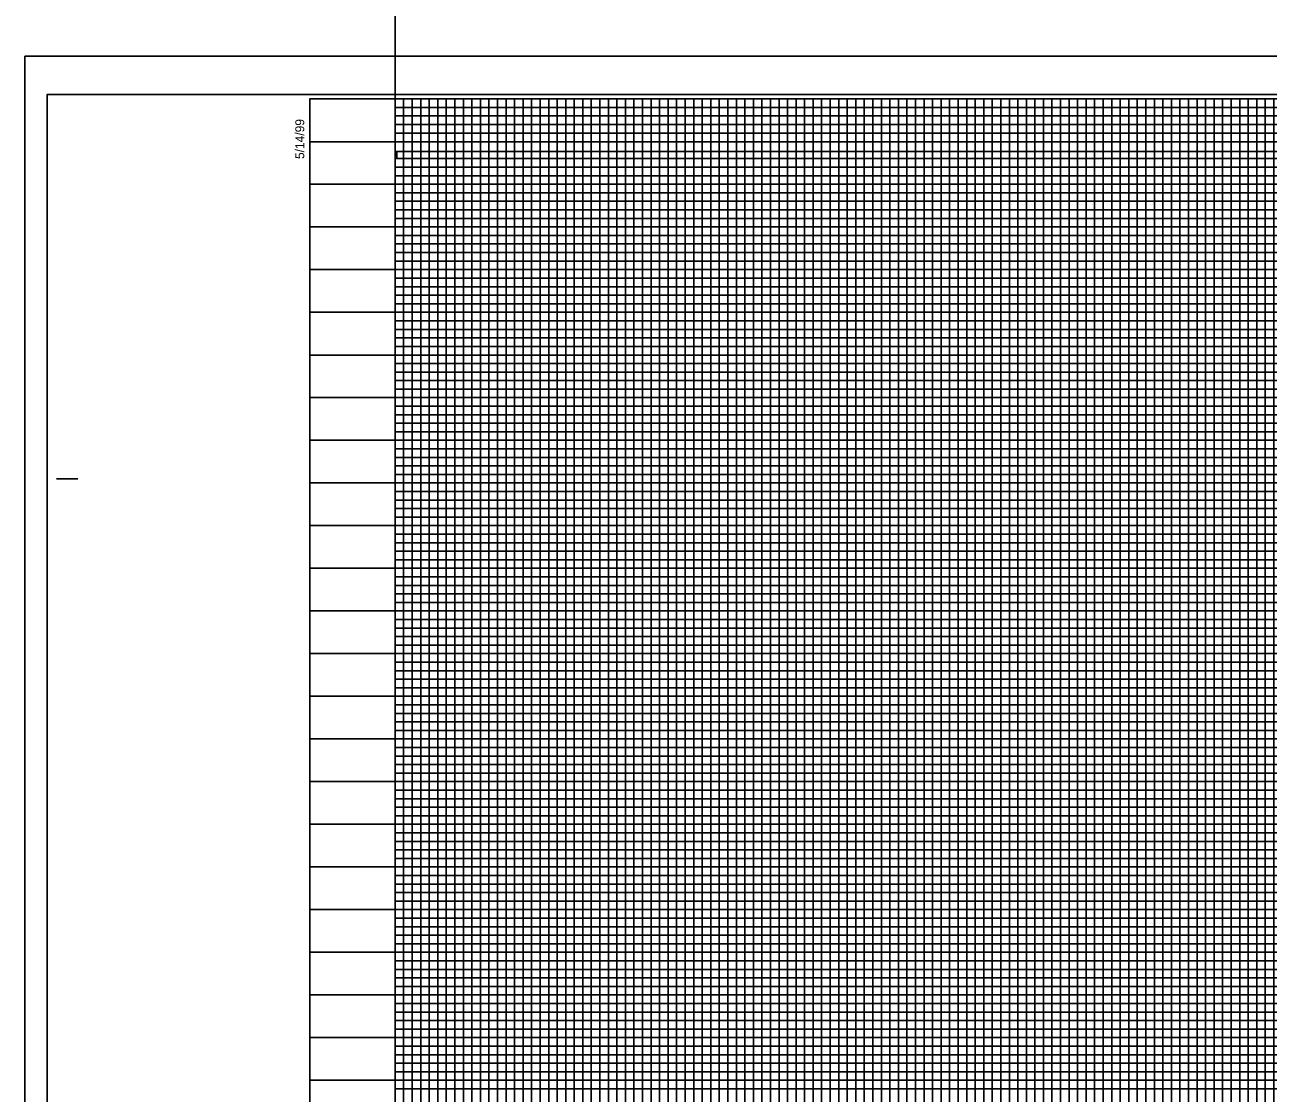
# Model space of a CAD drawing. Extents: x 2345490 to 2436403, y 465165 to 573888.
# Drawn here: x 2381463 to 2382192, y 536643 to 537269 of the extents above; entities that cross this region are included whole.
import ezdxf

# ---------------------------------------------------------------- set-up
doc = ezdxf.new("R2010")
doc.units = 0
for name, color, linetype in [('Old_Level_18', 7, 'Continuous'), ('Old_Level_41', 7, 'Continuous'), ('Old_Level_42', 7, 'Continuous'), ('Old_Level_43', 7, 'Continuous'), ('Old_Level_50', 7, 'Continuous'), ('Old_Level_51', 7, 'Continuous'), ('Old_Level_63', 7, 'Continuous')]:
    doc.layers.add(name, color=color, linetype=linetype)

msp = doc.modelspace()

# ---------------------------------------------------------------- linework, layer by layer
at = {"layer": 'Old_Level_18'}
msp.add_lwpolyline([(2383130.454, 537225.68175), (2381630.454, 537225.68175), (2381630.454, 536175.68175), (2383130.454, 536175.68175)], close=True, dxfattribs=at)
at = {"layer": 'Old_Level_41'}
msp.add_line((2381481.954, 537003.18175), (2381494.454, 537003.18175), dxfattribs=at)
for points in [[(2381630.454, 537225.68175), (2381680.454, 537225.68175), (2381680.454, 536200.68175), (2381730.454, 536200.68175), (2381730.454, 537225.68175), (2381780.454, 537225.68175), (2381780.454, 536200.68175), (2381830.454, 536200.68175), (2381830.454, 537225.68175), (2381880.454, 537225.68175), (2381880.454, 536200.68175), (2381930.454, 536200.68175), (2381930.454, 537225.68175), (2381980.454, 537225.68175), (2381980.454, 536200.68175), (2382030.454, 536200.68175), (2382030.454, 537225.68175), (2382080.454, 537225.68175), (2382080.454, 536200.68175), (2382130.454, 536200.68175), (2382130.454, 537225.68175), (2382180.454, 537225.68175), (2382180.454, 536200.68175), (2382230.454, 536200.68175)], [(2381705.454, 536200.68175), (2381705.454, 537225.68175), (2381755.454, 537225.68175), (2381755.454, 536200.68175), (2381805.454, 536200.68175), (2381805.454, 537225.68175), (2381855.454, 537225.68175), (2381855.454, 536200.68175), (2381905.454, 536200.68175), (2381905.454, 537225.68175), (2381955.454, 537225.68175), (2381955.454, 536200.68175), (2382005.454, 536200.68175), (2382005.454, 537225.68175), (2382055.454, 537225.68175), (2382055.454, 536200.68175), (2382105.454, 536200.68175), (2382105.454, 537225.68175), (2382155.454, 537225.68175), (2382155.454, 536200.68175), (2382205.454, 536200.68175)], [(2381630.454, 537175.68175), (2382930.404, 537175.68175)], [(2382930.404, 537125.68175), (2381630.454, 537125.68175), (2381630.454, 537075.63175), (2383130.454, 537075.63175)], [(2383130.454, 537050.68175), (2381630.454, 537050.68175), (2381630.454, 537100.68175), (2382930.404, 537100.68175)], [(2383130.454, 537025.68175), (2381630.454, 537025.68175), (2381630.454, 536975.68175), (2383130.454, 536975.68175)], [(2383130.454, 536950.68175), (2381630.454, 536950.68175), (2381630.454, 537000.68175), (2383130.454, 537000.68175)], [(2383130.454, 536925.68175), (2381630.454, 536925.68175), (2381630.454, 536875.68175), (2383130.454, 536875.68175)], [(2383130.454, 536825.68175), (2381630.454, 536825.68175), (2381630.454, 536775.68175), (2383130.454, 536775.68175)], [(2383130.454, 536725.68175), (2381630.454, 536725.68175), (2381630.454, 536675.68175), (2383130.454, 536675.68175)]]:
    msp.add_lwpolyline(points, dxfattribs=at)
at = {"layer": 'Old_Level_42'}
for points in [[(2382930.404, 537150.68175), (2381630.554, 537150.68175), (2381630.554, 537200.63175), (2382930.404, 537200.63175)], [(2383130.454, 536850.68175), (2381630.454, 536850.68175), (2381630.454, 536900.68175), (2383130.454, 536900.68175)], [(2383130.454, 536750.68175), (2381630.454, 536750.68175), (2381630.454, 536800.68175), (2383130.454, 536800.68175)], [(2383130.454, 536650.68175), (2381630.454, 536650.68175), (2381630.454, 536700.68175), (2383130.454, 536700.68175)]]:
    msp.add_lwpolyline(points, dxfattribs=at)
at = {"layer": 'Old_Level_43'}
for p, q in [((2383080.454, 537045.68175), (2381680.454, 537045.68175)), ((2381680.454, 537045.68175), (2381680.454, 537040.68175)), ((2381680.454, 537040.68175), (2383080.454, 537040.68175)), ((2383080.454, 537020.68175), (2381680.454, 537020.68175))]:
    msp.add_line(p, q, dxfattribs=at)
for points in [[(2381685.454, 537225.68175), (2381690.454, 537225.68175), (2381695.454, 537225.68175), (2381700.454, 537225.68175), (2381710.454, 537225.68175), (2381677.404, 537225.68175), (2381682.404, 537225.68175), (2381640.454, 537225.68175), (2381645.454, 537225.68175), (2381650.454, 537225.68175), (2381660.454, 537225.68175), (2381665.454, 537225.68175), (2381670.454, 537225.68175), (2381675.454, 537225.68175), (2381685.454, 537225.68175), (2381685.454, 536200.68175)], [(2382930.404, 537220.68175), (2381680.454, 537220.68175), (2381680.454, 537215.68175), (2382930.404, 537215.68175)], [(2381690.454, 536200.68175), (2381690.454, 537225.68175), (2381695.454, 537225.68175), (2381695.454, 536200.68175)], [(2381700.454, 536200.68175), (2381700.454, 537225.68175), (2381710.454, 537225.68175), (2381710.454, 536200.68175)], [(2381715.454, 536200.68175), (2381715.454, 537225.68175), (2381720.454, 537225.68175), (2381720.454, 536200.68175)], [(2381725.454, 536200.68175), (2381725.454, 537225.68175), (2381735.454, 537225.68175), (2381735.454, 536200.68175)], [(2381740.454, 536200.68175), (2381740.454, 537225.68175), (2381745.454, 537225.68175), (2381745.454, 536200.68175)], [(2381750.454, 536200.68175), (2381750.454, 537225.68175), (2381760.454, 537225.68175), (2381760.454, 536200.68175)], [(2381765.454, 536200.68175), (2381765.454, 537225.68175), (2381770.454, 537225.68175), (2381770.454, 536200.68175)], [(2381775.454, 536200.68175), (2381775.454, 537225.68175), (2381785.454, 537225.68175), (2381785.454, 536200.68175)], [(2381790.454, 536200.68175), (2381790.454, 537225.68175), (2381795.454, 537225.68175), (2381795.454, 536200.68175)], [(2381800.454, 536200.68175), (2381800.454, 537225.68175), (2381810.454, 537225.68175), (2381810.454, 536200.68175)], [(2381815.454, 536200.68175), (2381815.454, 537225.68175), (2381820.454, 537225.68175), (2381820.454, 536200.68175)], [(2381825.454, 536200.68175), (2381825.454, 537225.68175), (2381835.454, 537225.68175), (2381835.454, 536200.68175)], [(2381840.454, 536200.68175), (2381840.454, 537225.68175), (2381845.454, 537225.68175), (2381845.454, 536200.68175)], [(2381850.454, 536200.68175), (2381850.454, 537225.68175), (2381860.454, 537225.68175), (2381860.454, 536200.68175)], [(2381865.454, 536200.68175), (2381865.454, 537225.68175), (2381870.454, 537225.68175), (2381870.454, 536200.68175)], [(2381875.454, 536200.68175), (2381875.454, 537225.68175), (2381885.454, 537225.68175), (2381885.454, 536200.68175)], [(2381890.454, 536200.68175), (2381890.454, 537225.68175), (2381890.454, 537225.68175), (2381895.454, 537225.68175), (2381895.454, 536200.68175)], [(2381900.454, 536200.68175), (2381900.454, 537225.68175), (2381910.454, 537225.68175), (2381910.454, 536200.68175)], [(2381915.454, 536200.68175), (2381915.454, 537225.68175), (2381920.454, 537225.68175), (2381920.454, 536200.68175)], [(2381925.454, 536200.68175), (2381925.454, 537225.68175), (2381935.454, 537225.68175), (2381935.454, 536200.68175)], [(2381940.454, 536200.68175), (2381940.454, 537225.68175), (2381945.454, 537225.68175), (2381945.454, 536200.68175)], [(2381950.454, 536200.68175), (2381950.454, 537225.68175), (2381960.454, 537225.68175), (2381960.454, 536200.68175)], [(2381965.454, 536200.68175), (2381965.454, 537225.68175), (2381970.454, 537225.68175), (2381970.454, 536200.68175)], [(2381975.454, 536200.68175), (2381975.454, 537225.68175), (2381985.454, 537225.68175), (2381985.454, 536200.68175)], [(2381990.454, 536200.68175), (2381990.454, 537225.68175), (2381995.454, 537225.68175), (2381995.454, 536200.68175)], [(2382000.454, 536200.68175), (2382000.454, 537225.68175), (2382010.454, 537225.68175), (2382010.454, 536200.68175)], [(2382015.454, 537225.68175), (2382015.454, 536200.68175), (2382020.454, 536200.68175), (2382020.454, 537225.68175)], [(2382015.454, 537225.08175), (2382015.454, 536200.68175), (2382020.454, 536200.68175), (2382020.454, 537225.08175)], [(2382025.454, 536200.68175), (2382025.454, 537225.68175), (2382035.454, 537225.68175), (2382035.454, 536200.68175)], [(2382040.454, 536200.68175), (2382040.454, 537225.68175), (2382045.454, 537225.68175), (2382045.454, 536200.68175)], [(2382050.454, 536200.68175), (2382050.454, 537225.68175), (2382060.454, 537225.68175), (2382060.454, 536200.68175)], [(2382065.454, 536200.68175), (2382065.454, 537225.68175), (2382070.454, 537225.68175), (2382070.454, 536200.68175)], [(2382075.454, 536200.68175), (2382075.454, 537225.68175), (2382085.454, 537225.68175), (2382085.454, 536200.68175)], [(2382090.454, 536200.68175), (2382090.454, 537225.68175), (2382095.454, 537225.68175), (2382095.454, 536200.68175)], [(2382100.454, 536200.68175), (2382100.454, 537225.68175), (2382110.454, 537225.68175), (2382110.454, 536200.68175)], [(2382115.454, 536200.68175), (2382115.454, 537225.68175), (2382120.454, 537225.68175), (2382120.454, 536200.68175)], [(2382125.454, 536200.68175), (2382125.454, 537225.68175), (2382135.454, 537225.68175), (2382135.454, 536200.68175)], [(2382140.454, 536200.68175), (2382140.454, 537225.68175), (2382145.454, 537225.68175), (2382145.454, 536200.68175)], [(2382150.454, 536200.68175), (2382150.454, 537225.68175), (2382160.454, 537225.68175), (2382160.454, 536200.68175)], [(2382165.454, 537225.68175), (2382165.454, 536200.68175), (2382170.454, 536200.68175), (2382170.454, 537225.68175), (2382175.454, 537225.68175), (2382175.454, 536200.68175), (2382185.454, 536200.68175), (2382185.454, 537225.68175), (2382190.454, 537225.68175), (2382190.454, 536200.68175), (2382195.454, 536200.68175), (2382195.454, 537225.68175), (2382200.454, 537225.68175), (2382200.454, 536200.68175)], [(2382930.404, 537210.68175), (2381680.454, 537210.68175), (2381680.454, 537205.68175), (2382930.404, 537205.68175)], [(2382930.404, 537194.93175), (2381681.454, 537194.93175), (2381681.454, 537190.68175), (2382930.404, 537190.68175)], [(2382930.404, 537185.68175), (2381680.454, 537185.68175), (2381680.454, 537180.68175), (2382930.404, 537180.68175)], [(2382930.404, 537170.68175), (2381680.454, 537170.68175), (2381680.454, 537165.68175), (2382930.404, 537165.68175)], [(2382930.404, 537160.68175), (2381680.454, 537160.68175), (2381680.454, 537155.68175), (2382930.404, 537155.68175)], [(2382930.404, 537145.68175), (2381680.454, 537145.68175), (2381680.454, 537140.68175), (2382930.404, 537140.68175)], [(2382930.404, 537135.68175), (2381680.454, 537135.68175), (2381680.454, 537130.68175), (2382930.404, 537130.68175)], [(2382930.404, 537120.68175), (2381680.454, 537120.68175), (2381680.454, 537115.68175), (2382930.404, 537115.68175)], [(2382930.404, 537110.68175), (2381680.454, 537110.68175), (2381680.454, 537105.68175), (2382930.404, 537105.68175)], [(2382930.404, 537095.68175), (2381680.454, 537095.68175), (2381680.454, 537090.68175), (2382930.404, 537090.68175)], [(2383080.454, 537085.68175), (2381680.454, 537085.68175), (2381680.454, 537085.68175), (2381680.454, 537065.68175), (2383080.454, 537065.68175)], [(2381680.454, 537080.68175), (2383080.454, 537080.68175)], [(2383080.454, 537070.68175), (2381680.454, 537070.68175)], [(2383080.454, 537060.68175), (2381680.454, 537060.68175), (2381680.454, 537055.68175), (2383080.454, 537055.68175)], [(2383080.454, 537035.68175), (2381680.454, 537035.68175), (2381680.454, 537030.68175), (2383080.454, 537030.68175)], [(2383080.454, 537015.68175), (2381680.454, 537015.68175), (2381680.454, 537010.68175), (2383080.454, 537010.68175)], [(2383080.454, 537005.68175), (2381680.454, 537005.68175)], [(2381680.454, 536995.68175), (2383080.454, 536995.68175)], [(2383080.454, 536990.68175), (2381680.454, 536990.68175), (2381680.454, 536985.68175), (2383080.454, 536985.68175)], [(2383080.454, 536980.68175), (2381680.454, 536980.68175), (2381680.454, 536970.68175), (2383080.454, 536970.68175)], [(2383080.454, 536965.68175), (2381680.454, 536965.68175), (2381680.454, 536960.68175), (2383080.454, 536960.68175)], [(2383080.454, 536955.68175), (2381680.454, 536955.68175), (2381680.454, 536945.68175), (2383080.454, 536945.68175)], [(2383080.454, 536940.68175), (2381680.454, 536940.68175), (2381680.454, 536935.68175), (2383080.454, 536935.68175)], [(2383080.454, 536930.68175), (2381680.454, 536930.68175), (2381680.454, 536920.68175), (2383080.454, 536920.68175)], [(2383080.454, 536915.68175), (2381680.454, 536915.68175), (2381680.454, 536910.68175), (2383080.454, 536910.68175)], [(2383080.454, 536905.68175), (2381680.454, 536905.68175), (2381680.454, 536895.68175), (2383080.454, 536895.68175)], [(2383080.454, 536890.68175), (2381680.454, 536890.68175), (2381680.454, 536885.68175), (2383080.454, 536885.68175)], [(2383080.454, 536880.68175), (2381680.454, 536880.68175), (2381680.454, 536870.68175), (2383080.454, 536870.68175)], [(2383080.454, 536865.68175), (2381680.454, 536865.68175), (2381680.454, 536860.68175), (2383080.454, 536860.68175)], [(2383080.454, 536855.68175), (2381680.454, 536855.68175), (2381680.454, 536845.68175), (2383080.454, 536845.68175)], [(2383080.454, 536840.68175), (2381680.454, 536840.68175), (2381680.454, 536835.68175), (2383080.454, 536835.68175)], [(2383080.454, 536830.68175), (2381680.454, 536830.68175), (2381680.454, 536820.68175), (2383080.454, 536820.68175)], [(2383080.454, 536815.68175), (2381680.454, 536815.68175), (2381680.454, 536810.68175), (2383080.454, 536810.68175)], [(2383080.454, 536805.68175), (2381680.454, 536805.68175), (2381680.454, 536795.68175), (2383080.454, 536795.68175)], [(2383080.454, 536790.68175), (2381680.454, 536790.68175), (2381680.454, 536785.68175), (2383080.454, 536785.68175)], [(2383080.454, 536780.68175), (2381680.454, 536780.68175), (2381680.454, 536770.68175), (2383080.454, 536770.68175)], [(2383080.454, 536765.68175), (2381680.454, 536765.68175), (2381680.454, 536760.68175), (2383080.454, 536760.68175)], [(2383080.454, 536755.68175), (2381680.454, 536755.68175), (2381680.454, 536745.68175), (2383080.454, 536745.68175)], [(2383080.454, 536740.68175), (2381680.454, 536740.68175), (2381680.454, 536735.68175), (2383080.454, 536735.68175)], [(2383080.454, 536730.68175), (2381680.454, 536730.68175), (2381680.454, 536720.68175), (2383080.454, 536720.68175)], [(2383080.454, 536715.68175), (2381680.454, 536715.68175), (2381680.454, 536710.68175), (2383080.454, 536710.68175)], [(2383080.454, 536705.68175), (2381680.454, 536705.68175)], [(2381680.454, 536695.68175), (2383080.454, 536695.68175)], [(2383080.454, 536690.68175), (2381680.454, 536690.68175), (2381680.454, 536685.68175), (2383080.454, 536685.68175)], [(2383080.454, 536680.68175), (2381680.454, 536680.68175), (2381680.454, 536670.68175), (2383080.454, 536670.68175)], [(2383080.454, 536665.68175), (2381680.454, 536665.68175), (2381680.454, 536660.68175), (2383080.454, 536660.68175)], [(2383080.454, 536655.68175), (2381680.454, 536655.68175), (2381680.454, 536645.68175), (2383080.454, 536645.68175)]]:
    msp.add_lwpolyline(points, dxfattribs=at)
at = {"layer": 'Old_Level_50'}
msp.add_lwpolyline([(2383142.954, 537228.23175), (2381476.454, 537228.23175), (2381476.454, 536173.13175), (2383142.954, 536173.13175)], close=True, dxfattribs=at)
at = {"layer": 'Old_Level_51'}
msp.add_lwpolyline([(2383147.454, 537250.68175), (2381463.454, 537250.68175), (2381463.454, 536150.68175), (2383147.454, 536150.68175)], close=True, dxfattribs=at)
at = {"layer": 'Old_Level_63'}
msp.add_line((2381680.454, 536200.68175), (2381680.454, 538700.68175), dxfattribs=at)

# ---------------------------------------------------------------- texts
at = {"layer": 'Old_Level_41'}
msp.add_text('5/14/99', height=5.25, rotation=90, dxfattribs=at).set_placement((2381627.204, 537190.48175))

doc.saveas('drawing.dxf')
